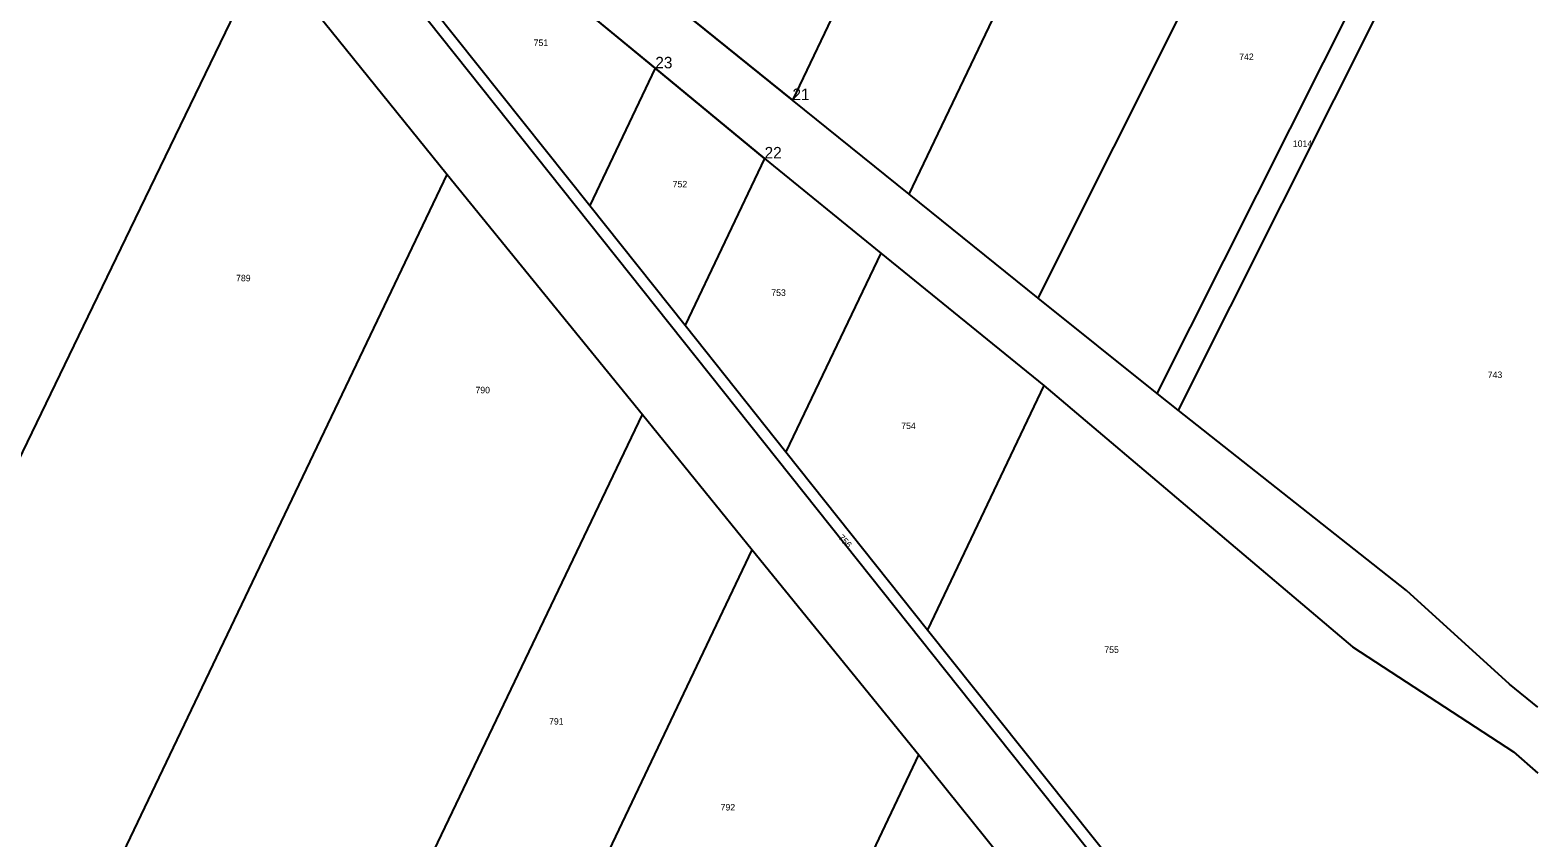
# Model space of a CAD drawing. Extents: x -504601 to -503665, y -1079870 to -1078626.
# Drawn here: x -504059.2 to -503665.3, y -1079659 to -1079448.1 of the extents above; entities that cross this region are included whole.
import ezdxf

# ---------------------------------------------------------------- set-up
doc = ezdxf.new("R2010")
doc.units = 0
for name, color, linetype in [('Hranice parcel', 7, 'Continuous'), ('Parcelní čísla', 7, 'Continuous'), ('Vrstva 31', 7, 'Continuous'), ('Vrstva 32', 7, 'Continuous'), ('Vrstva 54', 7, 'Continuous')]:
    doc.layers.add(name, color=color, linetype=linetype)

msp = doc.modelspace()

# ---------------------------------------------------------------- linework, layer by layer
at = {"layer": 'Hranice parcel'}
for p, q in [((-503775.28, -1079288.96), (-503860.04, -1079466.37)), ((-503829.57, -1079490.93), (-503746.84, -1079317.77)), ((-503795.86, -1079518.12), (-503713.84, -1079354.4)), ((-503764.74, -1079543.01), (-503689.81, -1079393.87)), ((-503686.06, -1079401.52), (-503759.31, -1079547.3)), ((-503942.64, -1079419.51), (-503895.86, -1079458.07)), ((-503997.67, -1079427.08), (-503950.22, -1079485.75)), ((-503953.77, -1079442.68), (-503912.97, -1079493.9)), ((-503860.04, -1079466.37), (-503888.76, -1079443.21)), ((-503895.86, -1079458.07), (-503912.97, -1079493.9)), ((-503895.86, -1079458.07), (-503867.31, -1079481.6)), ((-503829.57, -1079490.93), (-503860.04, -1079466.37)), ((-503867.31, -1079481.6), (-503888.1, -1079525.12)), ((-503867.31, -1079481.6), (-503836.94, -1079506.3)), ((-503950.22, -1079485.75), (-503899.25, -1079548.46)), ((-503795.86, -1079518.12), (-503829.57, -1079490.93)), ((-503912.97, -1079493.9), (-503888.1, -1079525.12)), ((-503836.94, -1079506.3), (-503861.75, -1079558.21)), ((-503836.94, -1079506.3), (-503794.37, -1079540.85)), ((-503764.74, -1079543.01), (-503795.86, -1079518.12)), ((-503888.1, -1079525.12), (-503861.75, -1079558.21)), ((-503794.37, -1079540.85), (-503824.73, -1079604.69)), ((-503759.31, -1079547.3), (-503764.74, -1079543.01)), ((-503899.25, -1079548.46), (-503870.57, -1079583.75)), ((-503861.75, -1079558.21), (-503824.73, -1079604.69)), ((-503870.57, -1079583.75), (-503827.05, -1079637.31)), ((-503827.05, -1079637.31), (-503785.46, -1079688.81))]:
    msp.add_line(p, q, dxfattribs=at)
for points in [[(-504131.58, -1079709.87), (-504110.18, -1079659.69), (-504032.95, -1079500.02), (-503997.67, -1079427.08)], [(-503697.84, -1079765.64), (-503779.17, -1079666.7), (-503806.76, -1079632.06), (-503843.08, -1079586.46), (-503955.21, -1079445.68)], [(-504133.72, -1079869.85), (-504130.18, -1079862.44), (-504053.56, -1079702.06), (-503975.76, -1079539.21), (-503950.22, -1079485.75)], [(-503794.37, -1079540.85), (-503713.69, -1079609.09), (-503671.67, -1079636.49), (-503665.31, -1079642.13)], [(-503665.31, -1079624.83), (-503672.75, -1079618.9), (-503699.64, -1079594.38), (-503759.31, -1079547.3)], [(-504052.8, -1079869.85), (-504043.32, -1079850.01), (-503965, -1079686.08), (-503899.25, -1079548.46)], [(-504006.66, -1079869.85), (-503993.46, -1079842.09), (-503916.36, -1079680.01), (-503870.57, -1079583.75)], [(-503824.73, -1079604.69), (-503775.32, -1079666.65), (-503696.41, -1079762.65)], [(-503937.05, -1079869.85), (-503919.87, -1079833.53), (-503842.14, -1079669.21), (-503827.05, -1079637.31)]]:
    msp.add_lwpolyline(points, dxfattribs=at)
at = {"layer": 'Vrstva 31'}
for p, q in [((-503895.86, -1079458.07), (-503895.86, -1079458.07)), ((-503860.04, -1079466.37), (-503860.04, -1079466.37)), ((-503867.31, -1079481.6), (-503867.31, -1079481.6))]:
    msp.add_line(p, q, dxfattribs=at)
at = {"layer": 'Vrstva 54'}
for points in [[(-503867.31, -1079481.6), (-503895.86, -1079458.07), (-503942.64, -1079419.51), (-503946.4, -1079416.88), (-503945.84, -1079414.89), (-503977.25, -1079388.9), (-504014.44, -1079358.14), (-504038.99, -1079330.47), (-504044.97, -1079331.7), (-504048.32, -1079336.41), (-504164.13, -1079193.65), (-504189.98, -1079161.66), (-504303.4, -1079021.3)], [(-504259.1, -1079048.24), (-504191.97, -1079119.35), (-504187.04, -1079125.02), (-504168.33, -1079151.66), (-504150.39, -1079177.22), (-504141.49, -1079189.89), (-504109.47, -1079227.67), (-504070.38, -1079273.8), (-504043.38, -1079305.66), (-504041.43, -1079307.47), (-504008.27, -1079338.19), (-503988.82, -1079356.2), (-503938.33, -1079402.97), (-503888.76, -1079443.21), (-503860.04, -1079466.37)]]:
    msp.add_lwpolyline(points, dxfattribs=at)

# ---------------------------------------------------------------- texts
at = {"layer": 'Parcelní čísla'}
for s, p in [('751', (-503927.65, -1079452.24)), ('742', (-503743.33, -1079455.91)), ('1014', (-503729.32, -1079478.59)), ('752', (-503891.32, -1079489.16)), ('789', (-504005.38, -1079513.68)), ('753', (-503865.56, -1079517.49)), ('743', (-503678.4, -1079538.93)), ('790', (-503942.85, -1079542.92)), ('754', (-503831.62, -1079552.25)), ('755', (-503778.56, -1079610.7)), ('791', (-503923.62, -1079629.42)), ('792', (-503878.8, -1079651.84))]:
    msp.add_text(s, height=1.7, dxfattribs=at).set_placement(p)
msp.add_text('756', height=1.7, rotation=314, dxfattribs=at).set_placement((-503848.21, -1079580.74))
at = {"layer": 'Vrstva 32'}
for s, p in [('23', (-503895.86, -1079458.07)), ('21', (-503860.04, -1079466.37)), ('22', (-503867.31, -1079481.6))]:
    msp.add_text(s, height=3, dxfattribs=at).set_placement(p)

doc.saveas('drawing.dxf')
